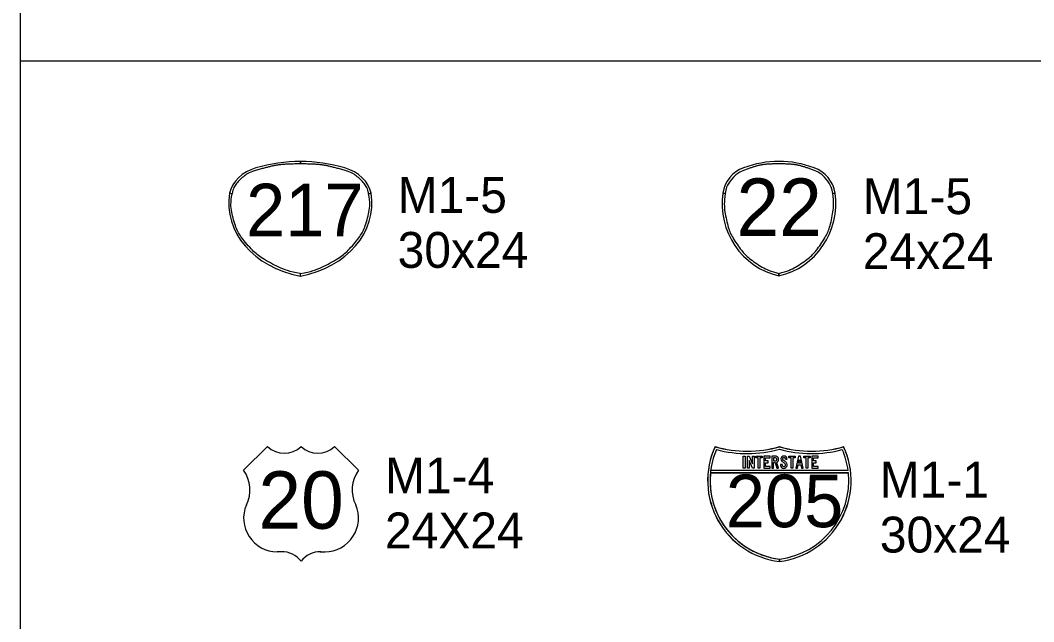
# Model space of a CAD drawing. Extents: x 1458 to 4498, y 17709 to 24109.
# Drawn here: x 1458.4 to 1882, y 20432.6 to 20684 of the extents above; entities that cross this region are included whole.
import ezdxf

# ---------------------------------------------------------------- set-up
doc = ezdxf.new("R2010")
doc.units = 0
doc.layers.add('P_ODOT_PLAN_TBlock', color=7, linetype='Continuous')
doc.layers.add('P_TRAF_TCP_General', color=7, linetype='Continuous')

msp = doc.modelspace()

# ---------------------------------------------------------------- linework, layer by layer
at = {"layer": 'P_ODOT_PLAN_TBlock'}
msp.add_line((1458.44, 20667.08), (3378.44, 20667.08), dxfattribs=at)
at = {"layer": 'P_TRAF_TCP_General'}
for p, q in [((1575.49, 20624.94), (1575.49, 20623.94)), ((1575.49, 20623.94), (1575.49, 20624.94)), ((1593.75, 20621.3), (1593.74, 20621.31)), ((1546.93, 20611.48), (1545.95, 20611.67)), ((1546.93, 20611.48), (1545.95, 20611.67)), ((1605.03, 20611.67), (1604.05, 20611.48)), ((1604.05, 20611.48), (1605.03, 20611.67)), ((1753.03, 20611.59), (1752, 20611.73)), ((1752, 20611.73), (1753.03, 20611.59)), ((1799.02, 20611.73), (1797.99, 20611.59)), ((1797.99, 20611.59), (1799.02, 20611.73)), ((1575.49, 20577.08), (1575.52, 20578.1)), ((1575.49, 20577.08), (1575.52, 20578.1)), ((1575.52, 20578.1), (1575.56, 20578.11)), ((1775.5, 20578.2), (1775.51, 20577.14)), ((1775.51, 20577.14), (1775.5, 20578.2)), ((1551.78, 20495.89), (1561.79, 20505.89)), ((1599.8, 20495.89), (1589.8, 20505.89)), ((1778.18, 20500.6), (1778.88, 20500.6)), ((1804.41, 20495.79), (1746.98, 20495.79)), ((1804.41, 20495.79), (1746.98, 20495.79)), ((1746.98, 20495.79), (1746.98, 20495.79)), ((1804.41, 20495.79), (1746.98, 20495.79)), ((1746.98, 20495.79), (1746.98, 20495.79)), ((1804.41, 20495.79), (1746.98, 20495.79)), ((1775.34, 20496.77), (1774.62, 20499.19)), ((1776.82, 20498.35), (1776.11, 20498.35)), ((1804.52, 20494.79), (1746.86, 20494.79)), ((1746.86, 20494.79), (1804.52, 20494.79)), ((1746.86, 20494.79), (1804.52, 20494.79)), ((1567.79, 20461.87), (1565.79, 20461.87)), ((1583.8, 20461.87), (1585.8, 20461.87)), ((1775.69, 20458.81), (1775.69, 20457.81)), ((1775.69, 20457.81), (1775.69, 20458.81)), ((1775.69, 20458.81), (1775.69, 20457.81)), ((1775.69, 20457.81), (1775.69, 20458.81)), ((1775.69, 20457.82), (1775.69, 20457.81)), ((1775.69, 20457.81), (1775.69, 20457.82)), ((1775.69, 20457.82), (1775.69, 20457.82))]:
    msp.add_line(p, q, dxfattribs=at)
for points in [[(4498.44, 21909.14), (1458.44, 21909.14), (1458.44, 19909.14), (4498.44, 19909.14)], [(1760.62, 20501.81), (1761.33, 20501.81), (1761.33, 20496.77), (1760.62, 20496.77)], [(1763, 20501.81), (1764.39, 20498.56), (1764.39, 20501.81), (1765.1, 20501.81), (1765.1, 20496.77), (1764.39, 20496.77), (1763.01, 20500.01), (1763.01, 20496.77), (1762.3, 20496.77), (1762.3, 20501.81)], [(1766.8, 20501.1), (1765.87, 20501.1), (1765.87, 20501.81), (1768.44, 20501.81), (1768.44, 20501.1), (1767.51, 20501.1), (1767.51, 20496.77), (1766.8, 20496.77)], [(1769.91, 20497.48), (1769.91, 20499.09), (1771.02, 20499.09), (1771.02, 20499.79), (1769.91, 20499.79), (1769.91, 20501.1), (1771.78, 20501.1), (1771.78, 20501.81), (1769.21, 20501.81), (1769.21, 20496.77), (1771.78, 20496.77), (1771.78, 20497.48)], [(1780.61, 20501.1), (1779.68, 20501.1), (1779.68, 20501.81), (1782.25, 20501.81), (1782.25, 20501.1), (1781.32, 20501.1), (1781.32, 20496.77), (1780.61, 20496.77)], [(1784.65, 20498.12), (1784.97, 20496.77), (1785.7, 20496.77), (1784.48, 20501.81), (1783.72, 20501.81), (1782.5, 20496.77), (1783.23, 20496.77), (1783.55, 20498.12)], [(1784.1, 20500.37), (1784.48, 20498.82), (1783.72, 20498.82)], [(1786.88, 20501.1), (1785.95, 20501.1), (1785.95, 20501.81), (1788.52, 20501.81), (1788.52, 20501.1), (1787.59, 20501.1), (1787.59, 20496.77), (1786.88, 20496.77)], [(1789.99, 20497.48), (1789.99, 20499.09), (1791.1, 20499.09), (1791.1, 20499.79), (1789.99, 20499.79), (1789.99, 20501.1), (1791.86, 20501.1), (1791.86, 20501.81), (1789.29, 20501.81), (1789.29, 20496.77), (1791.86, 20496.77), (1791.86, 20497.48)]]:
    msp.add_lwpolyline(points, close=True, dxfattribs=at)
for points in [[(1575.4, 20578.11), (1575.48, 20578.1), (1575.56, 20578.11)], [(1775.5, 20578.2), (1775.51, 20578.2), (1775.52, 20578.2)], [(1774.09, 20501.81), (1772.55, 20501.81), (1772.55, 20496.77), (1773.25, 20496.77), (1773.25, 20499.1), (1773.9, 20499.1), (1774.61, 20496.77), (1775.34, 20496.77)], [(1774.09, 20501.1), (1773.25, 20501.1), (1773.25, 20499.81), (1774.11, 20499.81)]]:
    msp.add_lwpolyline(points, dxfattribs=at)
for centre, radius, start, end in [((1568.79, 20513.06), 10.02, 225.6359, 314.3615), ((1582.8, 20513.06), 10.02, 225.6404, 314.2036), ((1779.69, 20491.56), 33.99, 155.2469, 263.2437), ((1779.69, 20491.56), 33.99, 155.2469, 263.2437), ((1779.69, 20491.56), 33.99, 155.2469, 263.2437), ((1779.69, 20491.56), 33.99, 155.2469, 263.2437), ((1779.69, 20491.56), 33.97, 155.2698, 263.2405), ((1779.69, 20491.56), 32.99, 156.7267, 263.0379), ((1779.69, 20491.56), 32.99, 156.7267, 263.0379), ((1779.69, 20491.56), 32.99, 156.7267, 172.6247), ((1779.69, 20491.56), 32.99, 156.7267, 172.6247), ((1762.26, 20551.85), 47.98, 253.7423, 286.2578), ((1762.26, 20551.85), 47.98, 253.7423, 286.2578), ((1762.26, 20551.85), 47.98, 253.7423, 286.2578), ((1762.26, 20551.85), 47.98, 253.7423, 286.2578), ((1762.26, 20551.85), 48, 253.7585, 286.2523), ((1762.26, 20551.85), 48.98, 254.7643, 285.9171), ((1762.26, 20551.85), 48.98, 254.7643, 285.9171), ((1762.26, 20551.85), 48.98, 254.7643, 285.9171), ((1762.26, 20551.85), 48.98, 254.7643, 285.9171), ((1771.69, 20491.56), 33.99, 276.7563, 24.7531), ((1789.13, 20551.85), 47.98, 253.7422, 286.2578), ((1771.69, 20491.56), 33.99, 276.7577, 24.7531), ((1789.13, 20551.85), 47.98, 253.7422, 286.2578), ((1771.69, 20491.56), 33.99, 276.7577, 24.7531), ((1789.13, 20551.85), 47.98, 253.7422, 286.2578), ((1789.13, 20551.85), 47.98, 253.7422, 286.2578), ((1771.69, 20491.56), 33.99, 276.7577, 24.7531), ((1771.69, 20491.56), 33.97, 276.7608, 24.7303), ((1789.13, 20551.85), 48, 253.7477, 286.2416), ((1789.13, 20551.85), 48.98, 254.0829, 285.2357), ((1789.13, 20551.85), 48.98, 254.0829, 285.2357), ((1789.13, 20551.85), 48.98, 254.0829, 285.2357), ((1789.13, 20551.85), 48.98, 254.0829, 285.2357), ((1771.69, 20491.56), 32.99, 7.3753, 23.2734), ((1771.69, 20491.56), 32.99, 7.3753, 23.2734), ((1771.69, 20491.56), 32.99, 7.3753, 23.2734), ((1771.69, 20491.56), 32.99, 7.3753, 23.2734), ((1774.11, 20500.6), 1.21, 32.7773, 91.1677), ((1774.11, 20500.58), 0.519, 26.159, 91.9542), ((1774.15, 20500.26), 0.455, 265.1381, 343.1073), ((1773.33, 20500.44), 1.3, 346.1097, 16.6195), ((1773.66, 20500.44), 1.68, 332.0334, 28.7465), ((1777.58, 20500.56), 1.31, 1.3681, 176.3683), ((1777.44, 20500.6), 1.17, 177.9393, 233.9136), ((1777.49, 20500.63), 0.507, 140.0639, 242.2325), ((1777.57, 20500.55), 0.615, 4.2694, 139.1342), ((1774.94, 20495.94), 4.83, 43.0003, 61.2981), ((1540.42, 20487.7), 14.01, 333.3525, 35.7886), ((1611.17, 20487.7), 14.01, 144.2114, 206.6475), ((1779.69, 20491.56), 32.99, 172.6245, 174.3721), ((1779.69, 20491.56), 32.99, 172.6245, 174.3721), ((1774.12, 20500.28), 1.2, 294.5283, 328.7975), ((1777.75, 20498.28), 1.65, 177.4542, 244.795), ((1774.32, 20495.17), 5.1, 45.9941, 61.57), ((1777.82, 20498.3), 1, 177.3621, 220.757), ((1777.53, 20498.07), 1.37, 249.6288, 333.604), ((1777.56, 20498.06), 0.639, 219.5909, 332.3646), ((1777.34, 20498.15), 0.872, 333.7597, 52.7126), ((1777.35, 20498.14), 1.56, 334.1366, 44.3106), ((1779.69, 20491.56), 32.99, 174.3723, 263.0379), ((1771.69, 20491.56), 32.99, 276.9621, 5.6278), ((1771.69, 20491.56), 32.99, 276.9634, 5.6278), ((1771.69, 20491.56), 32.99, 276.9634, 5.6278), ((1565.8, 20475.88), 14.01, 156.7159, 269.9338), ((1585.78, 20475.88), 14.01, 270.0662, 23.2841), ((1567.79, 20451.86), 10, 36.912, 91.107), ((1583.79, 20451.86), 10, 88.893, 143.088)]:
    msp.add_arc(centre, radius, start, end, dxfattribs=at)
for centre, major_axis, ratio, start_param, end_param in [((1575.49, 20581.83), (-53.44, 0), 0.806777, 4.712418, 5.066593), ((1575.49, 20581.83), (53.44, 0), 0.806777, 1.216593, 1.570768), ((1775.51, 20581.88), (0, 43.11), 0.986381, 0.000035, 0.354204), ((1775.51, 20581.88), (0, 43.11), 0.986381, 5.928982, 6.283151), ((1562.43, 20609.54), (-16.69, 0), 0.806777, 5.04665, 6.124248), ((1588.55, 20609.54), (16.69, 0), 0.806777, 0.158937, 1.236535), ((1765.12, 20609.6), (0, -13.47), 0.986381, 3.475854, 4.553452), ((1785.9, 20609.6), (0, -13.47), 0.986381, 1.729734, 2.807332), ((1584.1, 20607.37), (-38.53, 0), 0.806777, 6.14442, 7.628433), ((1566.87, 20607.37), (38.53, 0), 0.806777, 4.937938, 6.421951), ((1782.37, 20607.43), (0, -31.08), 0.986381, 4.573624, 6.057627), ((1768.65, 20607.43), (0, -31.08), 0.986381, 0.225558, 1.709562)]:
    msp.add_ellipse(centre, major_axis=major_axis, ratio=ratio, start_param=start_param, end_param=end_param, dxfattribs=at)
for points, degree in [([(1575.49, 20623.94), (1569.26, 20623.94), (1563.08, 20623.05), (1557.24, 20621.31)], 2), ([(1593.74, 20621.31), (1587.9, 20623.05), (1581.72, 20623.94), (1575.49, 20623.94)], 2), ([(1775.51, 20623.96), (1770.6, 20623.96), (1765.73, 20623.08), (1761.13, 20621.35)], 2), ([(1789.9, 20621.35), (1785.29, 20623.08), (1780.42, 20623.96), (1775.51, 20623.96)], 2), ([(1557.22, 20621.3), (1554.53, 20620.55), (1552.13, 20619.2), (1548.53, 20615.74), (1547.36, 20613.65), (1546.93, 20611.48)], 3), ([(1604.05, 20611.48), (1603.62, 20613.65), (1602.44, 20615.74), (1598.85, 20619.2), (1596.44, 20620.55), (1593.75, 20621.3)], 3), ([(1761.11, 20621.34), (1759.03, 20620.61), (1757.16, 20619.3), (1754.32, 20615.88), (1753.38, 20613.78), (1753.03, 20611.57)], 3), ([(1798, 20611.57), (1797.65, 20613.78), (1796.7, 20615.88), (1793.87, 20619.3), (1792, 20620.61), (1789.92, 20621.34)], 3), ([(1575.4, 20578.11), (1570.93, 20578.97), (1566.71, 20580.47), (1559.11, 20584.64), (1555.75, 20587.33), (1550.53, 20593.45), (1548.62, 20596.91), (1546.52, 20604.1), (1546.3, 20607.83), (1546.93, 20611.5)], 3), ([(1575.56, 20578.11), (1580.04, 20578.96), (1584.26, 20580.47), (1591.87, 20584.64), (1595.23, 20587.33), (1600.45, 20593.45), (1602.35, 20596.91), (1604.46, 20604.1), (1604.68, 20607.83), (1604.04, 20611.5)], 3), ([(1753.03, 20611.59), (1752.52, 20607.89), (1752.7, 20604.13), (1754.38, 20596.9), (1755.9, 20593.43), (1760.05, 20587.33), (1762.71, 20584.65), (1768.7, 20580.53), (1772.01, 20579.05), (1775.5, 20578.2)], 3), ([(1775.52, 20578.2), (1779.02, 20579.05), (1782.32, 20580.53), (1788.31, 20584.65), (1790.97, 20587.33), (1795.12, 20593.43), (1796.64, 20596.9), (1798.33, 20604.13), (1798.5, 20607.89), (1797.99, 20611.59)], 3)]:
    msp.add_open_spline(points, degree=degree, dxfattribs=at)

# ---------------------------------------------------------------- texts
for s, height, p in [('217', 21.991, (1552.83, 20593.67)), ('M1-5', 14.994, (1616.15, 20603.5)), ('22', 23.99, (1757.77, 20593.86)), ('M1-5', 14.994, (1810.55, 20602.97)), ('30x24', 14.994, (1616.15, 20580.51)), ('24x24', 14.994, (1810.55, 20579.98)), ('M1-4', 14.994, (1610.85, 20486.25)), ('20', 23.99, (1557.96, 20471.48)), ('M1-1', 14.994, (1817.66, 20484.52)), ('205', 21.991, (1753.31, 20472.11)), ('24X24', 14.994, (1610.85, 20463.26)), ('30x24', 14.994, (1817.66, 20461.53))]:
    msp.add_text(s, height=height, dxfattribs=at).set_placement(p)

doc.saveas('drawing.dxf')
